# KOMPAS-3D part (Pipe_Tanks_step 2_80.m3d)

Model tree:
1. X Axis
2. Y Axis
3. Z Axis  (labels: Bend 90 Dn 50; Pipe Dn 50)
     Òîëùèíà ñòåíêè 1 = 1

Referenced files in C:\Documents and Settings\kashirsky\Мои документы\Camtasia Studio\Pipelines3D\Tanks\: Tanks_step 4.a3d
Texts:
  Pipe Dn 50
  Steel ASTM A295
  Three Point Plane
  Plane at Angle
  Line and Point Plane
  Axis through Two Vertices
  Axis of Feature
  Axis of Conical Surface
  Axis through Edge
  Trim by Surface
  Trim by Sketch
  Feature with No History
  Intersection Axis of Two Planes
  Two Line Plane
  Line and Face Plane
  Bend by line
  Hole in sheet body
  Cut in sheet body
  Point in CM
  Linear Dimension from Line to Point
  Surface Finish Symbol
  Geometric Tolerance Symbol
  Leader #1
  Leader #2
  Leader #3
  Shape Deviations and Datum
  Node point number
  Mark of coordination axis
  Node point designation
  Mark/Reference designation with leader
  Mark/reference designation on line
  Mark/Reference designation without leader
  Bend 90 Dn 50
  Plane of section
